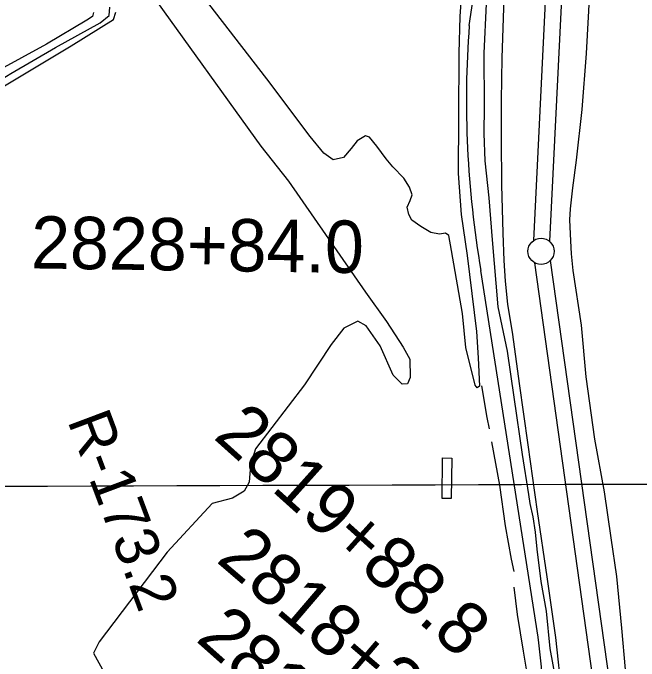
# Model space of a CAD drawing. Extents: x 3392644 to 3430565, y 576657 to 602123.
# Drawn here: x 3399740 to 3400936, y 587781 to 589018 of the extents above; entities that cross this region are included whole.
import ezdxf

# ---------------------------------------------------------------- set-up
doc = ezdxf.new("R2010")
doc.units = 0
for name, color, linetype in [('V-BLDG-OTLN', 7, 'Continuous'), ('V-GRID-MAJR', 7, 'Continuous'), ('V-LEVE-TOET', 7, 'Continuous'), ('V-RIVR-RANG-IDEN', 7, 'Continuous'), ('V-ROAD-CNTR', 7, 'Continuous'), ('V-SITE-VEGE', 7, 'Continuous'), ('V-SURV-IDEN', 7, 'Continuous'), ('V-SURV-LINE', 7, 'Continuous'), ('V-TOPO-SHOR', 7, 'Continuous')]:
    doc.layers.add(name, color=color, linetype=linetype)

msp = doc.modelspace()

# ---------------------------------------------------------------- linework, layer by layer
at = {"layer": 'V-BLDG-OTLN'}
msp.add_lwpolyline([(3400560.268, 588169.02), (3400577.787, 588168.81), (3400576.855, 588091.379), (3400559.335, 588091.59)], close=True, dxfattribs=at)
at = {"layer": 'V-GRID-MAJR'}
msp.add_spline([(3396759.069, 588105.428), (3402028.4020000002, 588122.6730000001), (3407297.732, 588140.684), (3412567.059, 588159.461), (3417836.383, 588179.004), (3423105.705, 588199.314), (3428375.023, 588220.3910000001), (3428375.024, 588220.3910000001)], degree=3, dxfattribs=at)
at = {"layer": 'V-LEVE-TOET'}
for points in [[(3400678.2660000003, 589066.098), (3400673.875, 588932.89), (3400672.429, 588851.275), (3400672.0130000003, 588778.022), (3400672.822, 588690.566), (3400675.43, 588597.741), (3400677.367, 588546.088), (3400680.146, 588506.519), (3400684.498, 588462.278), (3400693.806, 588404.723), (3400706.87, 588311.305), (3400723.367, 588193.893), (3400741.377, 588066.93), (3400759.643, 587942.053), (3400776.16, 587826.269), (3400788.0670000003, 587714.029), (3400791.711, 587688.171), (3400796.741, 587642.2930000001), (3400801.099, 587598.519), (3400801.492, 587592.701), (3400800.935, 587585.031), (3400798.473, 587573.667)], [(3400913.032, 587498.194), (3400914.241, 587506.98), (3400915.164, 587530.169), (3400915.252, 587595.519), (3400913.153, 587672.292), (3400909.616, 587765.128), (3400903.1240000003, 587844.0480000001), (3400893.378, 587942.54), (3400882.64, 588016.625), (3400869.508, 588104.461), (3400851.181, 588204.9180000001), (3400834.698, 588323.493), (3400825.654, 588422.442), (3400809.934, 588527.054), (3400806.592, 588558.491), (3400805.723, 588583.153), (3400803.417, 588623.414), (3400804.605, 588644.795), (3400809.27, 588684.742), (3400816.187, 588737.682), (3400826.877, 588833.838), (3400835.372, 588940.715), (3400841.434, 589058.09)]]:
    msp.add_lwpolyline(points, dxfattribs=at)
at = {"layer": 'V-ROAD-CNTR'}
for points in [[(3400611.378739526, 588994.764984), (3400621.57671913, 589062.851847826)], [(3400742.8094766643, 587827.0103195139), (3400633.633695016, 588526.651920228)]]:
    msp.add_lwpolyline(points, dxfattribs=at)
for centre, radius, start, end in [((3402510.837510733, 588850.4831926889), 1904.930670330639, 175.656178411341, 189.78759785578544), ((3399599.168181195, 587668.5808066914), 1154.562827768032, 358.8328247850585, 7.887035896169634)]:
    msp.add_arc(centre, radius, start, end, dxfattribs=at)
at = {"layer": 'V-SITE-VEGE'}
for points in [[(3400605.2630000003, 589184.257), (3400593.319, 589011.533), (3400591.693, 588941.694), (3400591.015, 588819.746), (3400590.116, 588712.011), (3400595.883, 588633.796), (3400607.174, 588555.12), (3400625.17, 588410.451), (3400628.512, 588360.285), (3400631.021, 588306.185), (3400626.64, 588303.078), (3400622.358, 588307.8690000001), (3400605.068, 588379.907), (3400598.74, 588444.712), (3400577.293, 588564.9500000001), (3400572.511, 588593.821), (3400566.244, 588597.843), (3400554.782, 588596.401), (3400537.847, 588599.367), (3400519.04, 588611.036), (3400501.816, 588622.691), (3400495.636, 588633.816), (3400492.643, 588647.667), (3400498.72, 588660.618), (3400502.398, 588671.231), (3400497.444, 588685.893), (3400486.6, 588702.993), (3400465.1550000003, 588724.958), (3400452.3140000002, 588740.111), (3400434.4450000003, 588764.007), (3400420.843, 588781.536), (3400412.978, 588784), (3400397.471, 588774.319), (3400385.846, 588759.463), (3400371.041, 588742.669), (3400351.643, 588737.7710000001), (3400333.252, 588751.017), (3400307.185, 588782.509), (3400224.441, 588892.435), (3400091.926, 589064.529)], [(3400002.639, 589057.314), (3400213.038, 588764.294), (3400265.909, 588697.353), (3400413.343, 588485.211), (3400453.324, 588429.475), (3400485.095, 588380.153), (3400497.847, 588357.504), (3400498.218, 588322.768), (3400493.332, 588310.1950000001), (3400483.063, 588309.53), (3400465.907, 588327.101), (3400441.3140000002, 588382.653), (3400414.146, 588420.8690000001), (3400398.468, 588429.741), (3400371.469, 588416.6460000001), (3400347.412, 588385.361), (3400296.7600000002, 588308.61), (3400202.937, 588186.596), (3400193.0870000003, 588155.139), (3400191.1180000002, 588122.799), (3400181.44, 588105.551), (3400159.178, 588092.397), (3400120.372, 588081.8150000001), (3400034.002, 587988.917), (3399904.0670000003, 587817.606), (3399893.5500000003, 587796.42), (3399913.625, 587759.078)], [(3399620.867, 588817.987), (3399850.651, 588955.735), (3399931.77, 589006.067), (3399935.889, 589020.225)], [(3399893.253, 589019.551), (3399891.58, 589011.678), (3399880.4450000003, 589004.707), (3399803.328, 588959.061), (3399659.503, 588880.272)]]:
    msp.add_lwpolyline(points, dxfattribs=at)
at = {"layer": 'V-SURV-LINE'}
for points in [[(3400734.4491641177, 588584.0728859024), (3400783.4238731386, 589574.4791724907)], [(3400813.3878115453, 589573.0086219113), (3400764.41313426, 588582.6029771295)], [(3400855.184997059, 587694.6244670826), (3400736.365556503, 588541.504598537)], [(3400766.076952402, 588545.6558931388), (3400884.8964689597, 587698.7752199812)]]:
    msp.add_lwpolyline(points, dxfattribs=at)
msp.add_circle((3400748.4441000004, 588563.3746300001), 25, dxfattribs=at)
at = {"layer": 'V-TOPO-SHOR'}
for points in [[(3400775.978, 587749.529), (3400766.197, 587805.464), (3400758.961, 587876.49), (3400748.592, 587932.853), (3400741.088, 587994.549), (3400738.201, 588027.444), (3400733.521, 588056.376), (3400727.776, 588082.05), (3400725.165, 588099.382), (3400713.0330000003, 588175.803), (3400697.31, 588285.1240000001), (3400684.441, 588372.708), (3400666.3200000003, 588457.18), (3400655.6520000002, 588585.514), (3400649.068, 588665.478), (3400641.828, 588736.116), (3400639.575, 588788.26), (3400640.738, 588839.816), (3400639.643, 588941.338), (3400644.279, 589036.025)], [(3399334.026, 588019.953), (3399365.1890000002, 588085.921), (3399406.417, 588173.258), (3399436.703, 588244.1410000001), (3399484.847, 588343.311), (3399517.1950000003, 588410.899), (3399548.542, 588472.892), (3399582.1210000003, 588545.607), (3399622.62, 588630.617), (3399628.856, 588644.091), (3399629.852, 588668.608), (3399617.523, 588692.35), (3399587.2800000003, 588741.535), (3399572.674, 588770.209), (3399573.573, 588786.783), (3399599.928, 588822.208), (3399635.205, 588841.872), (3399735.451, 588902.807), (3399820.615, 588952.706), (3399906.44, 588999.562), (3399923.433, 589013.843), (3399924.79, 589029.711)], [(3400634.64, 588306.845), (3400645.054, 588246.062), (3400649.213, 588224.349)], [(3400653.823, 588199.767), (3400668.843, 588116.952), (3400679.759, 588039.151), (3400691.553, 587976.005), (3400696.397, 587951.873)], [(3400696.7430000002, 587922.435), (3400702.721, 587870.395), (3400714.432, 587800.21), (3400723.412, 587746.954), (3400729.6520000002, 587700.0650000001), (3400733.015, 587657.672), (3400731.735, 587629.176), (3400730.967, 587621.381)]]:
    msp.add_lwpolyline(points, dxfattribs=at)

# ---------------------------------------------------------------- texts
at = {"layer": 'V-RIVR-RANG-IDEN'}
msp.add_text('R-173.2', height=82.99999799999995, rotation=290.56145945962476, dxfattribs=at).set_placement((3399843.002789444, 588240.2980194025))
at = {"layer": 'V-SURV-IDEN'}
for s, height, rotation, p in [('2828+84.0', 100.00000000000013, 359.17361181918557, (3399773.575455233, 588530.8310214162)), ('2819+88.8', 100.00000000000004, 318.11924879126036, (3400120.420746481, 588207.576630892)), ('2818+27.1', 99.99999999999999, 319.4490193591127, (3400125.7282898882, 587972.0761165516)), ('2815+82.1', 100.00000000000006, 318.3896116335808, (3400086.7540293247, 587820.9727007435))]:
    msp.add_text(s, height=height, rotation=rotation, dxfattribs=at).set_placement(p)

doc.saveas('drawing.dxf')
